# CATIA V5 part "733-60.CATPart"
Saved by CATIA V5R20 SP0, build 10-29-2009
Part number: 733-60
Bounding box of the stored display mesh (mm): x -47.5 to 47.5, y -47.5 to 47.5, z -60 to 90
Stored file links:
  C:\Users\Utente\Desktop\IO LAVORO\3D X SITO CF\X SITO\733\733-60.CATPart
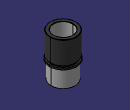
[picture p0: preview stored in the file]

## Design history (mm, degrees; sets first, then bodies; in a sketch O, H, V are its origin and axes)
Set1
  DatumSurface1 to DatumSurface25 "733-60"
Body1 (main body)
